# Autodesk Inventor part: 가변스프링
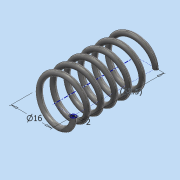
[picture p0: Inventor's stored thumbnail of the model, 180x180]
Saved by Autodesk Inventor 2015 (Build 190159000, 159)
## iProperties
Created: 2018-07
Part Number: 가변스프링
Material: 스테인레스 스틸
Document SubType Name: Modeling
Designer: SCD-A03
Density: 8 g/cm^3
Appearance: 반연마
Mass: 7.48085 g
Surface Area: 18.9515 cm^2
Volume: 0.935106 cm^3
Author: SCD-A03
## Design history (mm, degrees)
sketch "스케치1"
  geometry: L1 (0, 0)-(8, 0); L2 (8, 0)-(8, 32.5); L3 (8, 32.5)-(0, 32.5); L4 (0, 32.5)-(0, 0); C1 r 1 at (8, 0)
  constraints: 8 end point, 2 parallel, 1 centre point, 1 coincident, 1 horizontal, 1 perpendicular
  dimensions: "d0" = 16 diameter of L2 L4; "d1" = 32.5 distance of L1.end L2.end (derived); "d2" = 2 diameter of C1
feature "코일1" pitch "d3" = 10; turns "d5" = 6; dims "d4" = 32.5 (= d1), "d6" = 0, angle "d7" = 90 deg, angle "d8" = 90 deg, "d9" = 0, "d10" = 0
node "작업 평면1"
node "작업 평면2"
sketch "스케치2"
  geometry: L1 (9, 0)-(7, 0) reference; 1 further point
  constraints: 1 horizontal alignment
extrude "돌출1" cut sketch "스케치2" distance "d11" = 10; taper "d12" = 0 deg
sketch "스케치3"
  geometry: L1 (7, 0)-(9, 0) reference; 1 further point
  constraints: 1 horizontal alignment
extrude "돌출2" cut sketch "스케치3" distance "d13" = 10; taper "d14" = 0 deg
node "솔리드1"
node "절단 모서리 투영1"
node "절단 모서리 투영2"
